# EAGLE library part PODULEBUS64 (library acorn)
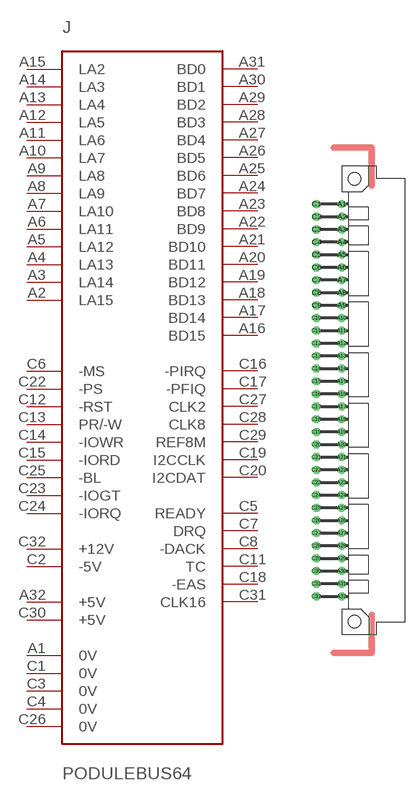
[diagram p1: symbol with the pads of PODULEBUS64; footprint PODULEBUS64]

Designator prefix J

## PODULEBUS64  [PODULEBUS64]
A1  0V  pwr
A2  LA15  out
A3  LA14  out
A4  LA13  out
A5  LA12  out
A6  LA11  out
A7  LA10  out
A8  LA9  out
A9  LA8  out
A10  LA7  out
A11  LA6  out
A12  LA5  out
A13  LA4  out
A14  LA3  out
A15  LA2  out
A16  BD15
A17  BD14
A18  BD13
A19  BD12
A20  BD11
A21  BD10
A22  BD9
A23  BD8
A24  BD7
A25  BD6
A26  BD5
A27  BD4
A28  BD3
A29  BD2
A30  BD1
A31  BD0
A32  +5V  pwr
C1  0V  pwr
C2  -5V  pwr
C3  0V  pwr
C4  0V  pwr
C5  READY  oc
C6  -MS  out
C7  DRQ  pas
C8  -DACK  out
C11  TC  out
C12  -RST  oc
C13  PR/-W  out
C14  -IOWR  out
C15  -IORD  out
C16  -PIRQ  oc
C17  -PFIQ  oc
C18  -EAS  out
C19  I2CCLK
C20  I2CDAT
C22  -PS  out
C23  -IOGT  pas
C24  -IORQ  out
C25  -BL  pas
C26  0V  pwr
C27  CLK2  out
C28  CLK8  out
C29  REF8M  out
C30  +5V  pwr
C31  CLK16  out
C32  +12V  pwr

## Footprint PODULEBUS64 (pad centres in mm)
Acorn Podule Bus 64 way, pre-Risc PC version
drill 0.914 pad 1.6 round: A1 -2.54,39.37
drill 0.914 pad 1.6 octagon: A2 -2.54,36.83; A3 -2.54,34.29; A4 -2.54,31.75; A5 -2.54,29.21; A6 -2.54,26.67; A7 -2.54,24.13; A8 -2.54,21.59; A9 -2.54,19.05; A10 -2.54,16.51; A11 -2.54,13.97; A12 -2.54,11.43; A13 -2.54,8.89; A14 -2.54,6.35; A15 -2.54,3.81; A16 -2.54,1.27; A17 -2.54,-1.27; A18 -2.54,-3.81; A19 -2.54,-6.35; A20 -2.54,-8.89; A21 -2.54,-11.43; A22 -2.54,-13.97; A23 -2.54,-16.51; A24 -2.54,-19.05; A25 -2.54,-21.59; A26 -2.54,-24.13; A27 -2.54,-26.67; A28 -2.54,-29.21; A29 -2.54,-31.75; A30 -2.54,-34.29; A31 -2.54,-36.83; A32 -2.54,-39.37; C1 -7.62,39.37; C2 -7.62,36.83; C3 -7.62,34.29; C4 -7.62,31.75; C5 -7.62,29.21; C6 -7.62,26.67; C7 -7.62,24.13; C8 -7.62,21.59; C9 -7.62,19.05; C10 -7.62,16.51; C11 -7.62,13.97; C12 -7.62,11.43; C13 -7.62,8.89; C14 -7.62,6.35; C15 -7.62,3.81; C16 -7.62,1.27; C17 -7.62,-1.27; C18 -7.62,-3.81; C19 -7.62,-6.35; C20 -7.62,-8.89; C21 -7.62,-11.43; C22 -7.62,-13.97; C23 -7.62,-16.51; C24 -7.62,-19.05; C25 -7.62,-21.59; C26 -7.62,-24.13; C27 -7.62,-26.67; C28 -7.62,-29.21; C29 -7.62,-31.75; C30 -7.62,-34.29; C31 -7.62,-36.83; C32 -7.62,-39.37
